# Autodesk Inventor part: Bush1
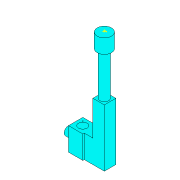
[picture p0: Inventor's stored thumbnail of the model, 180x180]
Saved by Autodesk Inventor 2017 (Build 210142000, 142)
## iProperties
Created: 2015-03
Part Number: Bush1
Document SubType Name: Modeling
Designer: Administrator
Density: 1 g/cm^3
Mass: 6.26946 g
Surface Area: 36.3049 cm^2
Volume: 6.26946 cm^3
Material: Generic
Appearance: Aqua
Author: Administrator
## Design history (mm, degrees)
sketch "Sketch1"
  geometry: L1 (0, 0)-(0, 3); L2 (5, 5)-(5, -5); L3 (5, -5)-(-5, -5); L4 (-5, -5)-(-5, 5); L5 (-5, 5)-(5, 5); 2 further points
  constraints: 10 end point, 2 coincident, 1 vertical, 1 vertical alignment, 12 other
  dimensions: "d0" = 3 distance of L1.start L1.end; "d5" = 10 distance of L4.end L2.start
extrude "Extrusion1" new body sketch "Sketch1" stored distance "d6" = 16; taper "d7" = 0 deg
sketch "Sketch2"
  geometry: L1 (-5, -5)-(-5, 5) reference; L2 (-5, 0)-(-10, 0); L3 (-10, 0)-(-10, 3); L4 (-10, 3)-(-6, 3); L5 (-6, 3)-(-6, 4); L6 (-6, 4)-(-5, 4); L7 (-5, 4)-(-5, 0)
  constraints: 12 end point, 3 parallel, 2 perpendicular, 1 collinear, 1 midpoint, 1 point on line
  dimensions: "d8" = 1 distance of L5.end L6.end; "d9" = 4 distance of L3.end L4.end; "d10" = 3 distance of L2.end L3.end; "d11" = 1 distance of L4.end L5.end
revolve "Revolution2" sketch "Sketch2" stored, may be unused: angle "d12" = 90 deg
sketch "Sketch3" dims "d13" = 8
  geometry: L1 (-5, 5)-(5, 5) reference; L2 (-2.828, 2.828)-(0, 0); C1 r 3 at (0, 0) reference; C2 r 0.25 at (-2.828, 2.828)
  constraints: 2 coincident, 2 end point, 1 centre point, 3 other
  dimensions: "d14" = 45 deg angle of L1 L2; "d15" = 0.5 diameter of C2
extrude "Extrusion2" cut sketch "Sketch3" distance "d16" = 20; taper "d17" = 0 deg
workpoint "Work Point2"
sketch "Sketch5"
  geometry: L1 (-5, 8)-(-5, -8) reference; L2 (5, -8)-(-5, -8) reference; L3 (-5, -8)-(-19, -8); L4 (-19, -8)-(-19, 32); L5 (-19, 32)-(-11, 32); L6 (-11, 32)-(-11, 8); L7 (-11, 8)-(-5, 8); L8 (-5, -8)-(-5, 8) reference; L9 (-5, 8)-(-5, -8); 1 further point
  constraints: 12 end point, 4 perpendicular, 1 collinear, 1 horizontal
  dimensions: "d24" = 6 distance between parallel lines of L6 L1; "d25" = 8 distance between parallel lines of L4 L6; "d26" = 40 distance of L3.end L4.end
extrude "Extrusion4" join sketch "Sketch5" stored distance "d27" = 8; taper "d28" = 0 deg
sketch "Sketch6"
  geometry: L1 (8, -8)-(8, 0) reference; L2 (0, 0)-(8, 0) reference; L3 (0, -8)-(0, 0) reference; L4 (8, -8)-(0, -8) reference; L5 (0, -4)-(8, -4); C1 r 3 at (4, -4); 1 further point
  constraints: 3 midpoint, 2 end point, 1 centre point
  dimensions: "d29" = 6 diameter of C1
extrude "Extrusion5" join sketch "Sketch6" distance "d30" = 30; taper "d31" = 0 deg
sketch "Sketch7"
  geometry: C1 r 3 at (0, 0) reference; C2 r 5 at (0, 0); 1 further point
  constraints: 1 centre point
  dimensions: "d32" = 10 diameter of C2
extrude "Extrusion6" join sketch "Sketch7" distance "d33" = 10; taper "d34" = 0 deg
workpoint "Work Point3"
  workaxis "Work Axis2"
body "Solid1"
node "Projected Loop1"
